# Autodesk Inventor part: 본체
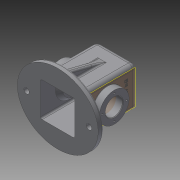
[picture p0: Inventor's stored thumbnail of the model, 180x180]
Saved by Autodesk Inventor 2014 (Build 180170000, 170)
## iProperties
Created: 2017-07
Part Number: 본체
Material: 일반
Document SubType Name: Modeling
Designer: 406-3333
Density: 1 g/cm^3
Appearance: 기본값
Author: 406-3333
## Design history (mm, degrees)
sketch "스케치1" dims "d0" = 65, "d1" = 75
  geometry: 2 further points; 1 other entity
  constraints: 1 coincident, 2 other
extrude "돌출1" new body sketch "스케치1" distance "d2" = 10; taper "d3" = 0 deg
sketch "스케치2"
  geometry: L1 (37, 37)-(-37, 37); L2 (-37, 37)-(-37, -37); L3 (-37, -37)-(37, -37); L4 (37, -37)-(37, 37); L5 (37, 37)-(-37, -37); L6 (-37, 37)-(37, -37); 1 further point; 1 other entity
  constraints: 12 end point, 2 midpoint, 2 parallel, 1 horizontal, 1 perpendicular, 1 other
  dimensions: "d4" = 74 distance between parallel lines of L4 L2; "d5" = 74 distance between parallel lines of L3 L1
extrude "돌출2" join sketch "스케치2" distance "d6" = 100; taper "d7" = 0 deg
node "작업 평면1"
sketch "스케치4"
  geometry: L1 (102, 0)-(102, -10) reference; L2 (102, -10)-(-28, -10) reference; L3 (-28, -10)-(-28, 0) reference; L4 (-28, 0)-(0, 0) reference; L5 (0, 0)-(0, 100) reference; L6 (0, 100)-(74, 100) reference; L7 (74, 100)-(74, 0) reference; L8 (74, 0)-(102, 0) reference; L9 (-18, 0)-(0, 72.194); L10 (74, 72.194)-(92, 0); L11 (-18, 0)-(0, 0); L12 (74, 72.194)-(74, 0); 1 further point
  constraints: 8 end point, 4 point on line, 1 collinear, 1 perpendicular
  dimensions: "d12" = 14 deg angle of L9 L3; "d13" = 14 deg angle of L1 L10; "d14" = 10 distance from line of L9.start L3; "d15" = 10 distance of L1.start L10.end
extrude "돌출4" join sketch "스케치4" stored distance "d16" = 10; taper "d17" = 0 deg
node "작업 평면2"
node "작업 평면4"
  node "작업 평면3"
sketch "스케치8"
  geometry: L1 (-11.448, 0)-(85.448, 0) reference; L2 (85.448, 0)-(85.448, -10) reference; L3 (85.448, -10)-(-11.448, -10) reference; L4 (-11.448, -10)-(-11.448, 0) reference; L5 (37, -10)-(37, 119.133); C1 r 27.5 at (37, 45)
  constraints: 2 end point, 1 centre point, 1 parallel, 1 point on line
  dimensions: "d29" = 55 distance from line of L3 C1.centre; "d30" = 55 diameter of C1
extrude "돌출8" join sketch "스케치8" distance "d31" = 100; taper "d32" = 0 deg
node "작업 평면5"
hole "구멍1" diameter "d45" = 32; stored, may be unused: countersink angle "d49" = 90 deg, drill point angle "d51" = 118 deg; dims "d43" = 10, "d44" = 10, "d46" = 6, "d47" = 4, "d48" = 2, "d50" = 8
sketch "스케치11" dims "d59" = 45
  geometry: L1 (0, 0)-(0, 47.659); C1 r 27.5 at (0, 0) reference; 3 further points
  constraints: 2 end point, 1 coincident, 1 point on line, 1 vertical, 1 vertical alignment, 2 other
hole "구멍3" sketch "스케치11" at (0, 22.5) diameter "d60" = 3.242; stored, may be unused: countersink angle "d64" = 90 deg, drill point angle "d66" = 118 deg; dims "d61" = 8, "d62" = 28, "d63" = 4, "d65" = 10
node "작업 평면6"
fillet "모깎기1" dims "d70" = 8
fillet "모깎기2" dims "d71" = 8
fillet "모깎기3" dims "d72" = 0.5
node "작업 평면7"
sketch "스케치12"
  geometry: L1 (20, 20)-(-20, 20); L2 (-20, 20)-(-20, -20); L3 (-20, -20)-(20, -20); L4 (20, -20)-(20, 20); L5 (20, 20)-(-20, -20); L6 (-20, 20)-(20, -20); 1 further point
  constraints: 12 end point, 2 midpoint, 2 parallel, 1 horizontal, 1 perpendicular
  dimensions: "d77" = 40 distance between parallel lines of L4 L2; "d78" = 40 distance between parallel lines of L3 L1
node "작업 평면8"
extrude "돌출10" join sketch "스케치12" distance "d84" = 10; taper "d85" = 0 deg
fillet "모깎기7" dims "d86" = 3
fillet "모깎기8" dims "d87" = 3
node "작업 평면9"
sketch "스케치14"
  geometry: 2 further points
  constraints: 1 coincident
hole "구멍4" sketch "스케치14" at (0, 0) diameter "d89" = 21; stored, may be unused: countersink angle "d93" = 90 deg, drill point angle "d95" = 118 deg; dims "d90" = 8, "d91" = 28, "d92" = 4, "d94" = 10
chamfer "모따기1" distance "d96" = 1; stored, may be unused: second distance "d97" = 2, angle "d98" = 5 deg
node "작업 평면10"
sketch "스케치15"
  geometry: L1 (12, 18)-(46, 18) reference; L2 (66, -92)-(66, 0) reference; 3 further points
  constraints: 1 other
  dimensions: "d101" = 30 distance from line of point (29, -12) L1; "d102" = 37 distance from line of L2 point (29, -12)
feature "엠보싱1" sketch "스케치15" dims "d103" = 0.5, "d104" = 0
fillet "모깎기10" dims "d105" = 3
fillet "모깎기11" dims "d106" = 3
fillet "모깎기12" dims "d107" = 3
sketch "스케치13"
  geometry: L1 (-72, 0)-(72, 0); L2 (-5, -37)-(-29, -37) reference; L3 (-37, -29)-(-37, 29) reference; L4 (-29, 37)-(-5, 37) reference; L5 (-5, 37)-(-5, 55) reference; L6 (-5, 55)-(5, 55) reference; L7 (5, 55)-(5, 37) reference; L8 (5, 37)-(29, 37) reference; L9 (37, 29)-(37, -29) reference; L10 (29, -37)-(5, -37) reference; L11 (5, -37)-(5, -55) reference; L12 (5, -55)-(-5, -55) reference; L13 (-5, -55)-(-5, -37) reference; C1 r 5 at (-58, 0); C2 r 5 at (58, 0); A1 r 8 centre (-29, -29) between (-37, -29) and (-29, -37) reference; A2 r 8 centre (-29, 29) between (-29, 37) and (-37, 29) reference; A3 r 8 centre (29, 29) between (37, 29) and (29, 37) reference; A4 r 8 centre (29, -29) between (29, -37) and (37, -29) reference; 2 further points; 1 other entity
  constraints: 2 centre point, 2 end point, 2 point on line, 1 other
  dimensions: "d80" = 58 distance of point (0, 0) C1.centre; "d81" = 58 distance of point (0, 0) C2.centre; "d82" = 10 diameter of C1; "d83" = 10 diameter of C2
extrude "돌출11" cut sketch "스케치13" stored distance "d108" = 10; taper "d109" = 0 deg
sketch "스케치16"
  geometry: L1 (32, 32)-(-32, 32); L2 (-32, 32)-(-32, -32); L3 (-32, -32)-(32, -32); L4 (32, -32)-(32, 32); L5 (32, 32)-(-32, -32); L6 (-32, 32)-(32, -32); C1 r 10.5 at (0, 0) reference; 1 further point; 1 other entity
  constraints: 12 end point, 2 midpoint, 2 parallel, 1 horizontal, 1 perpendicular, 1 other
  dimensions: "d110" = 64 distance of L3.end L2.end; "d111" = 64 distance of L2.end L1.end
extrude "돌출12" cut sketch "스케치16" distance "d112" = 105; taper "d113" = 0 deg
fillet "모깎기13" dims "d114" = 3
node "작업 평면11"
sketch "스케치17"
  geometry: L1 (-43, -92)-(-34, -92) reference; L2 (-34, -92)-(-34, -102) reference; L3 (-34, -102)-(-46, -102) reference; L4 (-46, -102)-(-46, -95) reference; L5 (104, -95)-(104, -102) reference; L6 (104, -102)-(92, -102) reference; L7 (92, -102)-(92, -92) reference; L8 (92, -92)-(101, -92) reference; L9 (68.026, -69.5)-(69, -71.121) reference; L10 (69, -71.121)-(79, -71.121) reference; L11 (79, -71.121)-(79, -74.5) reference; L12 (79, -74.5)-(66.5, -74.5) reference; L13 (66, -75)-(66, -89) reference; L14 (69, -92)-(82, -92) reference; L15 (82, -92)-(82, -102) reference; L16 (82, -102)-(61, -102) reference; L17 (61, -102)-(61, -63) reference; L18 (61, -63)-(78, -63) reference; L19 (78, -63)-(79, -64) reference; L20 (79, -64)-(79, -67.879) reference; L21 (79, -67.879)-(69, -67.879) reference; L22 (69, -67.879)-(68.026, -69.5) reference; L23 (69, -22.879)-(68.026, -24.5) reference; L24 (68.026, -24.5)-(69, -26.121) reference; L25 (69, -26.121)-(79, -26.121) reference; L26 (79, -26.121)-(79, -30) reference; L27 (79, -30)-(78, -31) reference; L28 (78, -31)-(61, -31) reference; L29 (61, -31)-(61, 0) reference; L30 (58, 3)-(39.5, 3) reference; L31 (39.5, 3)-(39.5, 14) reference; L32 (39.5, 14)-(43, 14) reference; L33 (43, 14)-(43, 18) reference; L34 (43, 18)-(49, 18) reference; L35 (49, 18)-(49, 11) reference; L36 (52, 8)-(58, 8) reference; L37 (66, 0)-(66, -9.615) reference; L38 (66, -9.615)-(66.5, -9.615) reference; L39 (66.5, -9.615)-(66.5, -10.029) reference; L40 (66.5, -10.029)-(66, -10.029) reference; L41 (66, -10.029)-(66, -19) reference; L42 (66.5, -19.5)-(79, -19.5) reference; L43 (79, -19.5)-(79, -22.879) reference; L44 (79, -22.879)-(69, -22.879) reference; L45 (-11, -71.121)-(-10.026, -69.5) reference; L46 (-10.026, -69.5)-(-11, -67.879) reference; L47 (-11, -67.879)-(-21, -67.879) reference; L48 (-21, -67.879)-(-21, -64) reference; L49 (-21, -64)-(-20, -63) reference; L50 (-20, -63)-(-3, -63) reference; L51 (-3, -63)-(-3, -102) reference; L52 (-3, -102)-(-24, -102) reference; L53 (-24, -102)-(-24, -92) reference; L54 (-24, -92)-(-11, -92) reference; L55 (-8, -89)-(-8, -75) reference; L56 (-8.5, -74.5)-(-21, -74.5) reference; L57 (-21, -74.5)-(-21, -71.121) reference; L58 (-21, -71.121)-(-11, -71.121) reference; L59 (-10.026, -24.5)-(-11, -22.879) reference; L60 (-11, -22.879)-(-21, -22.879) reference; L61 (-21, -22.879)-(-21, -19.5) reference; L62 (-21, -19.5)-(-8.5, -19.5) reference; L63 (-8, -19)-(-8, 0) reference; L64 (0, 8)-(6, 8) reference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; A1 r 0.5 centre (66.5, -75) between (66.5, -74.5) and (66, -75) reference; A2 r 3 centre (69, -89) between (66, -89) and (69, -92) reference; A3 r 3 centre (58, 0) between (61, 0) and (58, 3) reference; A4 r 3 centre (52, 11) between (49, 11) and (52, 8) reference; A5 r 8 centre (58, 0) between (66, 0) and (58, 8) reference; A6 r 0.5 centre (66.5, -19) between (66, -19) and (66.5, -19.5) reference; A7 r 3 centre (-11, -89) between (-11, -92) and (-8, -89) reference; A8 r 0.5 centre (-8.5, -75) between (-8, -75) and (-8.5, -74.5) reference; A9 r 0.5 centre (-8.5, -19) between (-8.5, -19.5) and (-8, -19) reference; A10 r 8 centre (0, 0) between (0, 8) and (-8, 0) reference; A11 r 3 centre (6, 11) between (6, 8) and (9, 11) reference; A12 r 3 centre (0, 0) between (0, 3) and (-3, 0) reference
  constraints: 39 end point, 8 perpendicular, 8 point on line, 7 parallel, 3 point on circle, 3 symmetric about line, 1 midpoint, 2 other
revolve "회전1" sketch "스케치17" stored, may be unused: angle "d118" = 90 deg
sketch "스케치18"
  geometry: C1 r 16 at (0, 0) reference; C2 r 16 at (0, 0); 1 further point
  constraints: 1 centre point, 1 coincident
  dimensions: "d119" = 32 diameter of C2
extrude "돌출13" cut sketch "스케치18" stored distance "d120" = 105; taper "d121" = 0 deg
fillet "모깎기14" dims "d122" = 3
node "솔리드1"
pattern_circular "원형 패턴1" dims angle "d68" = 360 deg
mirror "대칭1"
node "절단 모서리 투영1"
node "절단 모서리 투영5"
node "절단 모서리 투영7"
node "절단 모서리 투영8"
other parameters: "d33" = 32, "d34" = 32, "d36" = 7, "d39" = 135 deg, "d40" = 135 deg, "d76" = 0, "d79" = 0, "d88" = 0, "d100" = 0, "d115" = 27.5, "d116" = 27.5, "d117" = 7
